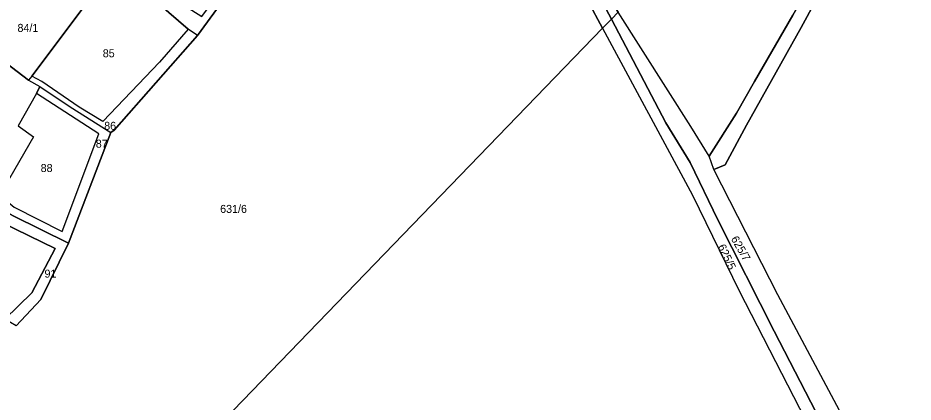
# Model space of a CAD drawing. Extents: x -629983 to -626385, y -1072828 to -1067897.
# Drawn here: x -627272.2 to -626936.7, y -1070443.1 to -1070299.1 of the extents above; entities that cross this region are included whole.
import ezdxf

# ---------------------------------------------------------------- set-up
doc = ezdxf.new("R2010")
doc.units = 0
for name, color, linetype in [('Parcela nároku', 7, 'Continuous'), ('Parcelní číslo', 7, 'Continuous'), ('Plocha PÚ', 7, 'Continuous'), ('Vnitřní obvod_šetřený', 7, 'Continuous')]:
    doc.layers.add(name, color=color, linetype=linetype)

msp = doc.modelspace()

# ---------------------------------------------------------------- linework, layer by layer
at = {"layer": 'Parcela nároku'}
for points in [[(-627050.81, -1070215.29), (-627048.81, -1070205.49), (-627052.04, -1070197.4), (-627012.93, -1070174.79), (-626992.65, -1070193.42), (-626988.98, -1070196.53), (-626951.03, -1070243.61), (-626981.69, -1070298.04), (-626996.16, -1070322.96), (-627002.91, -1070334.81), (-627013.07, -1070350.93), (-627019.98, -1070339.74), (-627047.18, -1070296.9), (-627061.62, -1070274.07), (-627080.79, -1070227.64)], [(-626951.03, -1070243.61), (-626948.34, -1070246.95), (-626957.81, -1070264.45), (-626978.64, -1070302.67), (-626999.11, -1070339.24), (-627007.09, -1070354.1), (-627011.37, -1070355.84), (-627013.07, -1070350.93), (-627002.91, -1070334.81), (-626996.16, -1070322.96), (-626981.69, -1070298.04)], [(-627075.48, -1070252.15), (-627061.62, -1070274.07), (-627056.32, -1070287), (-627049.73, -1070299.54), (-627053.04, -1070302.96), (-627058.48, -1070292.86)], [(-627190.33, -1070281.05), (-627187.83, -1070282.28), (-627204.91, -1070305.64), (-627208.37, -1070303.22), (-627237.36, -1070278.17), (-627245.28, -1070273.22), (-627249.14, -1070270.65), (-627241.87, -1070258.26), (-627237.64, -1070261.07), (-627235.99, -1070258.67), (-627233.2, -1070260.24), (-627219.92, -1070266.54), (-627216.29, -1070268.32), (-627227.51, -1070283.02), (-627203.32, -1070298.52)], [(-627061.62, -1070274.07), (-627047.18, -1070296.9), (-627049.73, -1070299.54), (-627056.32, -1070287)], [(-627237.36, -1070278.17), (-627208.37, -1070303.22), (-627219.15, -1070315.7), (-627240.38, -1070337.93), (-627249.2, -1070332.55), (-627263.25, -1070322.88), (-627266.97, -1070320.91), (-627245.44, -1070292.1)], [(-627269.14, -1070285.43), (-627254.18, -1070287.03), (-627245.44, -1070292.1), (-627266.97, -1070320.91), (-627268.23, -1070322.38), (-627288.54, -1070306.92), (-627279.99, -1070292.78), (-627280.63, -1070290.51), (-627278.26, -1070286.84), (-627272.3, -1070290.53)], [(-627047.18, -1070296.9), (-627049.73, -1070299.54), (-627029.32, -1070338.39), (-627020.26, -1070353.28), (-627009.85, -1070374.79), (-626988.77, -1070416.53), (-626959.42, -1070473.41), (-626956.06, -1070461.5), (-626987.37, -1070402.95), (-627011.37, -1070355.84), (-627013.07, -1070350.93), (-627019.98, -1070339.74)], [(-627020.26, -1070353.28), (-627029.32, -1070338.39), (-627049.73, -1070299.54), (-627053.04, -1070302.96), (-627019.31, -1070365.57), (-627001.79, -1070401.46), (-626961.16, -1070480.65), (-626959.42, -1070473.41), (-626988.77, -1070416.53), (-627009.85, -1070374.79)], [(-627266.97, -1070320.91), (-627268.23, -1070322.38), (-627264.04, -1070324.83), (-627252.64, -1070332.45), (-627237.32, -1070342.02), (-627236.14, -1070341.15), (-627204.91, -1070305.64), (-627208.37, -1070303.22), (-627219.15, -1070315.7), (-627240.38, -1070337.93), (-627249.2, -1070332.55), (-627263.25, -1070322.88)], [(-627053.04, -1070302.96), (-627019.31, -1070365.57), (-627001.79, -1070401.46), (-626961.16, -1070480.65), (-626963.5, -1070490.35), (-626965.53, -1070531.94), (-626993.73, -1070553.31), (-627043.31, -1070552.63), (-627195.27, -1070541.23), (-627254.93, -1070512.01), (-627152.6, -1070406.05)], [(-627273.58, -1070370.07), (-627255.6, -1070379.2), (-627241.89, -1070342.47), (-627265.18, -1070327.36), (-627264.04, -1070324.83), (-627252.64, -1070332.45), (-627237.32, -1070342.02), (-627253.21, -1070383.58), (-627273.96, -1070373.23), (-627281.46, -1070369.18), (-627279.05, -1070365.5)], [(-627266.34, -1070343.62), (-627279.05, -1070365.5), (-627273.58, -1070370.07), (-627255.6, -1070379.2), (-627241.89, -1070342.47), (-627265.18, -1070327.36), (-627272.15, -1070339.58)], [(-627282.42, -1070373.36), (-627277.92, -1070375.92), (-627258.19, -1070385.58), (-627267.02, -1070402.16), (-627277.05, -1070412), (-627283.29, -1070408.44), (-627309.64, -1070391.13), (-627314.46, -1070387.99), (-627302.71, -1070372.61), (-627293.97, -1070365.98)], [(-627290.51, -1070363.35), (-627281.46, -1070369.18), (-627273.96, -1070373.23), (-627253.21, -1070383.58), (-627263.63, -1070404.64), (-627272.9, -1070414.5), (-627277.05, -1070412), (-627267.02, -1070402.16), (-627258.19, -1070385.58), (-627277.92, -1070375.92), (-627282.42, -1070373.36), (-627293.97, -1070365.98)]]:
    msp.add_lwpolyline(points, close=True, dxfattribs=at)
for points in [[(-627272.9, -1070414.5), (-627263.63, -1070404.64), (-627253.21, -1070383.58), (-627237.32, -1070342.02), (-627236.14, -1070341.15), (-627204.91, -1070305.64), (-627187.83, -1070282.28), (-627184.44, -1070277.62), (-627184.08, -1070275.66), (-627182.9, -1070269.22), (-627183.96, -1070265.49), (-627167.2, -1070248.39), (-627135.2, -1070270.05), (-627091.2, -1070227.3), (-627075.48, -1070252.15), (-627058.48, -1070292.86), (-627053.04, -1070302.96), (-627152.6, -1070406.05), (-627254.93, -1070512.01), (-627269.4, -1070505.83), (-627296.3, -1070493.2)], [(-626911.31, -1070492.3), (-626939.59, -1070512.67), (-626959.42, -1070473.41), (-626956.06, -1070461.5), (-626987.37, -1070402.95), (-627011.37, -1070355.84), (-627007.09, -1070354.1), (-626999.11, -1070339.24), (-626978.64, -1070302.67), (-626957.81, -1070264.45), (-626948.34, -1070246.95), (-626933.51, -1070266.22)], [(-627288.54, -1070306.92), (-627268.23, -1070322.38), (-627264.04, -1070324.83), (-627265.18, -1070327.36), (-627272.15, -1070339.58), (-627266.34, -1070343.62), (-627279.05, -1070365.5)]]:
    msp.add_lwpolyline(points, dxfattribs=at)
at = {"layer": 'Plocha PÚ'}
msp.add_lwpolyline([(-627187.83, -1070282.28), (-627204.91, -1070305.64), (-627236.14, -1070341.15), (-627237.32, -1070342.02), (-627253.21, -1070383.58), (-627263.63, -1070404.64), (-627272.9, -1070414.5)], dxfattribs=at)
at = {"layer": 'Vnitřní obvod_šetřený'}
for p, q in [((-627187.83, -1070282.28), (-627204.91, -1070305.64)), ((-627204.91, -1070305.64), (-627236.14, -1070341.15)), ((-627237.32, -1070342.02), (-627253.21, -1070383.58)), ((-627236.14, -1070341.15), (-627237.32, -1070342.02)), ((-627253.21, -1070383.58), (-627263.63, -1070404.64)), ((-627263.63, -1070404.64), (-627272.9, -1070414.5))]:
    msp.add_line(p, q, dxfattribs=at)

# ---------------------------------------------------------------- texts
at = {"layer": 'Parcelní číslo'}
for s, p in [('84/1', (-627272.35, -1070304.3)), ('85', (-627240.39, -1070313.82)), ('86', (-627239.86, -1070341.02)), ('87', (-627243.02, -1070347.72)), ('88', (-627263.67, -1070356.84)), ('631/6', (-627196.39, -1070372.18)), ('91', (-627262.23, -1070396.45))]:
    msp.add_text(s, height=3, dxfattribs=at).set_placement(p)
for s, rotation, p in [('625/7', 299.9674, (-627005.05, -1070381.91)), ('625/5', 295.4393, (-627009.92, -1070384.77))]:
    msp.add_text(s, height=3, rotation=rotation, dxfattribs=at).set_placement(p)

doc.saveas('drawing.dxf')
